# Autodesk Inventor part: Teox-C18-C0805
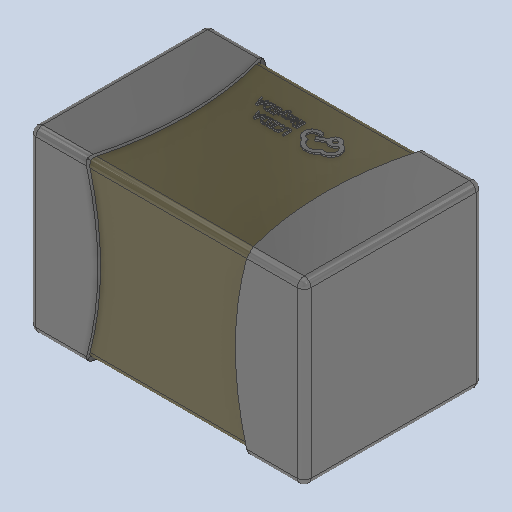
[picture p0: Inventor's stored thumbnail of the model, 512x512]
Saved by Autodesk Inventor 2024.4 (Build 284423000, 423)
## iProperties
Created: 2025-05
Part Number: Teox-C18-C0805
Material: Generic
Document SubType Name: Modeling
Designer: AdminForWorker
Density: 1 g/cm^3
Appearance: Default
Title: Teox-C18-C0805
Author: AdminForWorker
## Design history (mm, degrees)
feature "Body1"
body "Solid1"
